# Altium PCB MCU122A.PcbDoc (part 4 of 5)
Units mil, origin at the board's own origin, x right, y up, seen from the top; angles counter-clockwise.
Board outline 4950 x 3450 mil, 4 copper layers (Top Layer, Signal Layer 1, Signal Layer 2, Bottom Layer), stack 60 mil thick; 257 components, 158 nets, 848 pads, 1971 vias.
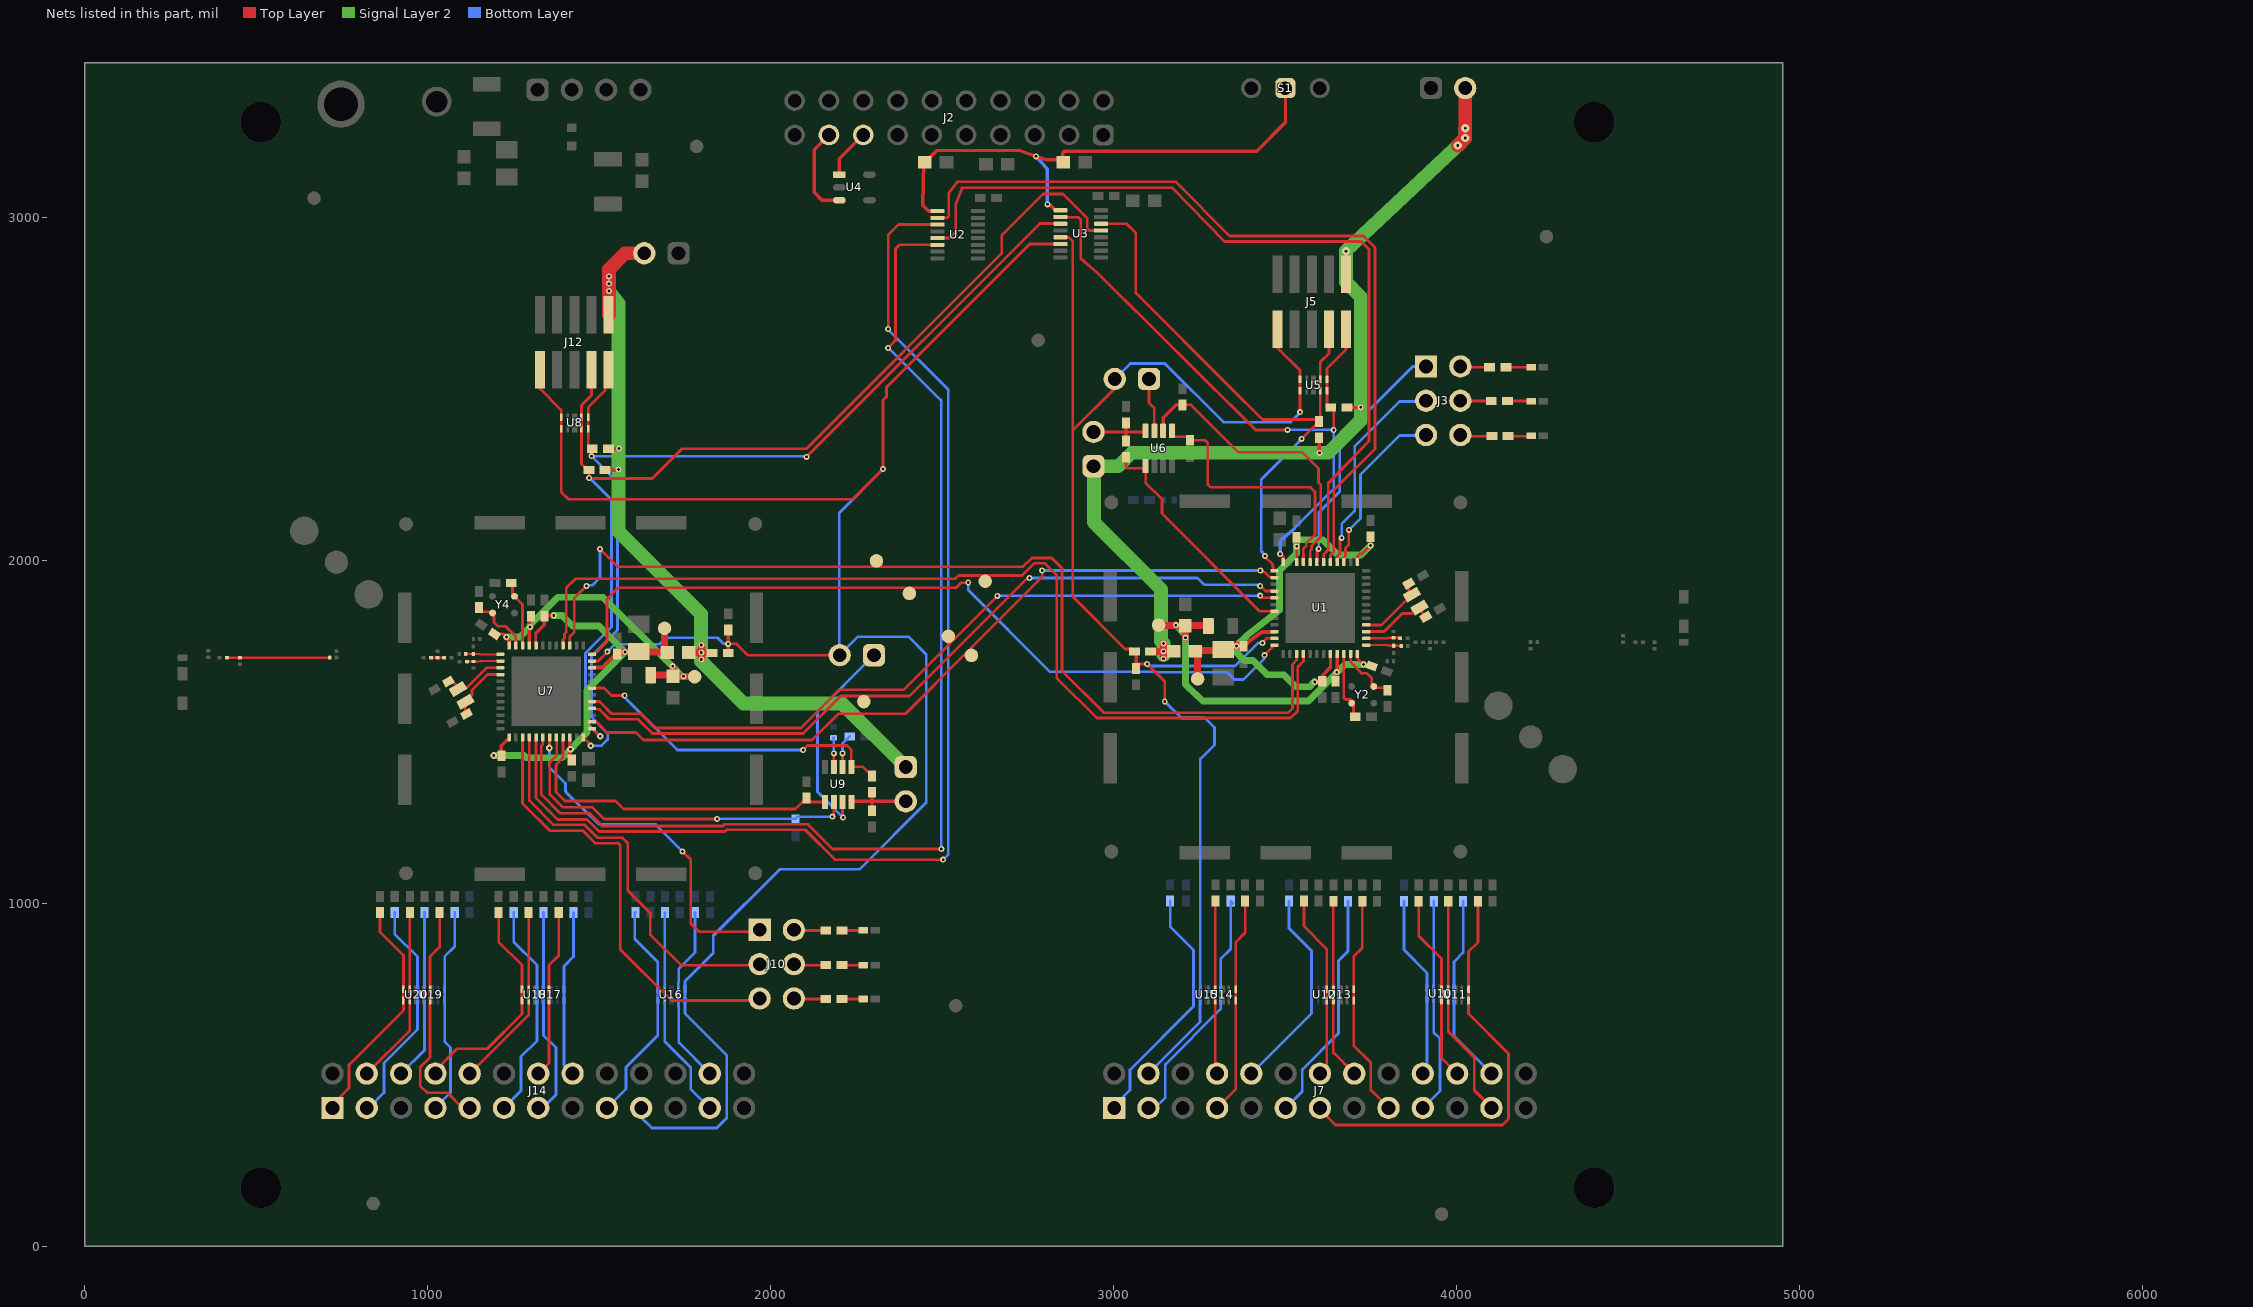
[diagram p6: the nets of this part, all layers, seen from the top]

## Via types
v1: diameter 17.46, hole 8, Top Layer to Bottom Layer, tented both sides, 1708 vias
v2: diameter 13.9, hole 8, Top Layer to Bottom Layer, tented both sides, 206 vias
v3: diameter 19.68, hole 8, Top Layer to Bottom Layer, tented both sides, 42 vias
v4: diameter 24, hole 8, Top Layer to Bottom Layer, tented both sides, 8 vias
v5: diameter 19.46, hole 8, Top Layer to Bottom Layer, tented both sides, 6 vias
v6: diameter 34, hole 8, Top Layer to Bottom Layer, tented both sides, 1 vias

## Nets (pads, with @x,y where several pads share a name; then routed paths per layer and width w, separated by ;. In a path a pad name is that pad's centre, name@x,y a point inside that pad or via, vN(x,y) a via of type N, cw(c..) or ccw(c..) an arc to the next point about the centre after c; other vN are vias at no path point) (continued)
NetC83_2: C83.2 C85.2 L11.1 | length 294.6
  Top Layer w6.5: L11.1@415.68,1715.3 C83.2@710.32,1715.3
NetC84_2: C84.2 L9.2 L10.1 | length 38
  Top Layer w6.5: L10.1@1010.16,1715.4 L9.2@1048.17,1715.4
NetC89_1: C89.1 U9.3 | length 85.3
  Top Layer w8: U9.3@2184.05,1397 v1(2184.05,1436.66)
  Bottom Layer w8: C89.1@2183,1481.9 2184.05,1480.84 v1(2184.05,1436.66)
NetC91_1: C91.1 U9.2 | length 103.2
  Top Layer w8: U9.2@2209.65,1397 v1(2209.65,1436.66)
  Bottom Layer w8: v1@2213.73,1440.75 v1(2209.65,1436.66) 2209.65,1465.33 C91.1@2230.22,1485.9
NetJ3_1: J3.1 U1.19 | length 725
  Top Layer w8: U1.19@3592.52,1994.09 3592.66,1994.23 3592.66,2027.71 v1(3597.57,2032.63)
  Bottom Layer w8: v1(3597.57,2032.63) 3597.57,2137.77 3659.13,2199.33 3659.13,2351.73 3871.94,2564.54 J3.1@3910.73,2564.54
NetJ3_2: J3.2 R12.1 | length 86.3
  Top Layer w8: J3.2@4010.73,2564.54 4013.06,2562.21 R12.1@4096.1,2562.21
NetJ3_3: J3.3 U1.16 | length 621.4
  Top Layer w8: U1.16@3650.87,1994.8 3650.87,2009.67 3659.69,2018.49 3659.69,2057.43 3664.66,2062.4 v1(3664.66,2064.96)
  Bottom Layer w8: v1(3664.66,2064.96) 3664.66,2104.91 3702.56,2142.8 3702.56,2331.55 3833.23,2462.21 3908.41,2462.21 J3.3@3910.73,2464.54
NetJ3_4: J3.4 R11.1 | length 90.3
  Top Layer w8: J3.4@4010.73,2464.54 4011.65,2463.62 R11.1@4100.65,2463.62
NetJ3_5: J3.5 U1.15 | length 513.5
  Top Layer w8: U1.15@3671.26,1994.09 3671.26,2007.61 3675.57,2011.92 3675.57,2034.53 3685.27,2044.23 3685.27,2087.51 v1(3685.89,2088.13)
  Bottom Layer w8: v1(3685.89,2088.13) 3719.38,2121.62 3719.38,2249.19 3833.23,2363.03 J3.5@3910.73,2363.03
NetJ3_6: J3.6 R10.1 | length 93.3
  Top Layer w8: J3.6@4010.73,2364.54 4013.99,2361.29 R10.1@4102.72,2361.29
NetJ8_1: J8.1 U6.7 | length 157.6
  Top Layer w8: J8.1@3103.15,2528 3103.15,2457.84 3118.43,2442.56 U6.7@3118.43,2376.74
NetJ10_1: J10.1 U7.19 | length 1020.8
  Top Layer w8: v5@1355.42,1450.42 U7.19@1355.42,1483.02 ; v1(1742.85,1150.5) 1766.87,1126.47 1766.87,940.29 1790.64,916.52 J10.1@1967.72,916.52
  Top Layer w10: v5@1355,1450 v5@1355.42,1450.42
  Bottom Layer w8: v5@1355,1450 1355.57,1398.12 1355.61,1394.85 1401.46,1349 1401.46,1325.49 1403.84,1323.12 1499.55,1229.49 1663.86,1229.49 v1(1742.85,1150.5)
  other v5: 1354.83,1451.79
NetJ10_2: J10.2 R36.1 | length 93.5
  Top Layer w8: J10.2@2067.72,921.8 2069.51,920.01 R36.1@2160.43,920.01
NetJ10_3: J10.3 U7.16 | length 1172.4
  Top Layer w8: U7.16@1296.36,1483.02 1296.36,1298.5 1366.97,1227.88 1458.01,1227.88 1495.73,1190.16 1567.86,1190.16 1583.23,1174.79 1583.23,1037.03 1648.6,971.66 1648.6,908.29 1738,818.9 J10.3@1967.72,818.9
NetJ10_4: J10.4 R35.1 | length 93.9
  Top Layer w8: J10.4@2067.72,821.8 2070.62,818.9 R35.1@2160.43,818.9
NetJ10_5: J10.5 U7.15 | length 1299.8
  Top Layer w8: U7.15@1276.68,1483.02 1276.68,1290.63 1356.6,1210.71 1452.73,1210.71 1489.34,1174.1 1556.78,1174.1 1561.47,1169.42 1561.47,1019.44 1561.47,865.08 1710.72,715.83 J10.5@1967.72,715.83
NetJ10_6: J10.6 R34.1 | length 93.3
  Top Layer w8: J10.6@2067.72,721.8 2069.05,720.48 R34.1@2160.43,720.48
NetJ15_1: J15.1 U9.7 | length 618.8
  Top Layer w8: U9.7@2209.65,1294.64 2209.65,1251.1 v1(2211.41,1249.33)
  Bottom Layer w8: v1(2211.41,1249.33) 2136.21,1324.53 2136.21,1557.74 J15.1@2301.14,1722.67
SW_CTRL: C10.1 C11.1 S1.1 U2.1 U3.1 | length 1597.5
  Top Layer w10: C10.1@2446.62,3160 2443.69,3034.98 2461.25,3017.41 U2.1@2485.91,3017.41 ; C10.1@2449.57,3160 2483.65,3194.07 2595.19,3194.07 2724.1,3194.16 v1(2773.31,3177.18) 2803.35,3166.81 2803.44,3166.9 2843.73,3166.9 2851.12,3174.29 2851.12,3187.26 2855.43,3191.57 3416.71,3191.57 3500.9,3275.76 S1.1@3500.9,3375.98 S1.1@3500.9,3384.19 ; v1(2806.73,3036.98) 2808.15,3035.56 2814.31,3035.56 2830.01,3019.86 U3.1@2838.47,3019.86
  Bottom Layer w10: v1(2773.31,3177.18) 2803.68,3143.17 2806.23,3140.32 2806.23,3037.48 v1(2806.73,3036.98)
VDDR_WM1: C26.1 C27.1 C28.1 L1.2 TP5.1 U1.45 U1.48 | length 1093.6
  Top Layer w8: C27.1@3647,1646.62 C27.1@3650,1649.62 ; U1.48@3710.63,1726.38 3710.63,1713.41 v1(3728.41,1695.63) ; v1(3728.41,1695.63) 3747.67,1695.63 C28.1@3752.22,1691.08 3732.96,1691.08 v1(3728.41,1695.63)
  Top Layer w10: C27.1@3650,1649.62 v1(3650,1672.95) ; v1@3651.57,1672.95 U1.45@3651.57,1726.38
  Top Layer w20: TP5.1@3131.94,1809.35 v1@3181.1,1809.35 ; v1@3183.31,1807.98 C26.1@3208.54,1807.98 3208.54,1774.43 v1(3209.4,1773.57) ; C26.1@3215.6,1809.29 L1.2@3267.17,1809.13
  Signal Layer 2 w20: v1(3181.1,1810.19) v1@3209.4,1781.89 ; v1@3209.4,1776.57 3209.4,1636.65 3213.6,1632.45 3259.76,1588.77 3556.86,1588.77 3568.21,1588.77 3675.07,1695.63 v1(3728.41,1695.63)
VDDR_WM2: C66.1 C67.1 C68.1 L7.2 TP13.1 U7.45 U7.48 | length 983.5
  Top Layer w10: C68.1@1194.85,1784.45 1220.65,1784.45 v1(1229.7,1775.4) ; 1222.1,1783 v1(1229.7,1775.4) ; U7.48@1237.31,1750.74 1237.31,1767.79 v1(1229.7,1775.4) ; U7.45@1296.36,1750.74 1296.36,1831.74 C67.1@1301,1836.38 ; C66.1@1710.85,1664.38 C66.1@1714.31,1660.93 ; TP13.1@1777.11,1660.93 TP13.1@1778.29,1659.75
  Top Layer w20: L7.2@1653.39,1664.38 C66.1@1710.85,1664.38 ; v1@1714.71,1690.46 C66.1@1714.71,1660.93 v1(1745.85,1660.93) TP13.1@1777.11,1660.93
  Signal Layer 2 w20: v1(1229.7,1775.4) 1268.4,1775.4 v1(1298,1805) 1298,1810.31 1379.15,1891.47 1511.02,1891.47 1713.17,1689.32 1741.56,1660.93 v1(1745.85,1660.93)
  other v1: 1714.31,1690.46
VDDS_WM1: C21.1 C22.1 C23.1 C24.1 C25.1 FB2.2 TP4.1 U1.13 U1.22 U1.34 U1.44 | length 1546.7
  Top Layer w8: U1.22@3533.46,1994.09 C25.1@3533.46,2076.77 ; 3631.89,1688.13 U1.44@3631.89,1726.38 ; U1.13@3710.63,1994.09 3710.63,2010.67 3717.68,2017.72 3723.12,2017.72 3747.72,2042.32 3747.72,2066.6 C23.1@3749.03,2067.91
  Top Layer w10: v1(3586.35,1644.58) 3588.39,1646.62 C24.1@3608,1646.62 3608,1662.83 3631.89,1686.72 3631.89,1688.13
  Top Layer w12: C21.1@3329.11,1750.39 3319.9,1741.18 C21.1@3342.11,1741.18 ; C22.1@3377.97,1750.39 3382.94,1750.39 3397.97,1765.42 3433.21,1790.5 U1.34@3468.5,1790.5
  Top Layer w20: TP4.1@3241.64,1653.57 3244.83,1656.76 3244.83,1736.22 C21.1@3304.15,1736.22 ; C21.1@3329.11,1750.39 C22.1@3377.97,1750.39
  Signal Layer 2 w20: v1@3585.48,1645.45 3570.52,1630.49 3531.22,1630.49 3496.28,1665.44 3448.17,1665.44 3406.01,1707.6 3380.54,1707.6 3356.32,1731.83 3356.32,1749.09 3357.21,1749.09 3387.3,1779.17 3483.11,1853.56 3483.11,1969.11 3533.46,2019.47 3533.46,2051.18 3541.51,2059.23 3608.59,2059.23 3653.32,2014.5 3720.66,2014.5 3748.49,2042.32 v1(3749.03,2042.32)
  other v1: 3358.32,1749.09 3533.46,2040
VDDS_WM2: C61.1 C62.1 C63.1 C64.1 C65.1 FB3.2 TP12.1 U7.13 U7.22 U7.34 U7.44 | length 1422
  Top Layer w8: 1314.94,1785.72 1314.94,1751.85 U7.44@1316.05,1750.74
  Top Layer w10: v5@1193.5,1427.58 1195.29,1429.37 C63.1@1214.77,1429.37 1214.77,1458.86 1237.31,1481.39 U7.13@1237.31,1483.02 ; 1314.66,1786 1339.44,1810.79 1340,1810.79 C64.1@1340,1836.38 1341.97,1838.35 v1@1363.65,1838.35 ; U7.22@1414.47,1483.02 1414.47,1418.15 C65.1@1420,1412.62
  Top Layer w12: U7.34@1479.43,1686.5 1509.19,1686.5 1551.02,1727.68 C62.1@1555.78,1732.37
  Top Layer w20: C62.1@1555.78,1732.37 1615.24,1732.37 1688.77,1732.37 1690.57,1730.57 1690.57,1800.95 TP12.1@1690.46,1801.06
  Signal Layer 2 w20: v5(1192.41,1430.32) 1280.44,1430.32 1287.36,1423.4 1390.9,1423.4 1464.83,1497.33 1464.83,1621.59 v1(1575.24,1732) 1499.74,1807.5 1422.75,1807.5 1392.91,1837.34 1392.91,1838.35 1365.45,1838.35 v1@1364.55,1837.45
  other v1: 1367.65,1838.35
  other v5: 1416.5,1448
WM1_2HOST_REV: J7.17 R1.2 U13.5 U13.6 | length 654.9
  Top Layer w8: R1.2@3724.87,1005.16 3724.73,1005.02 3724.73,869.35 3699.76,844.38 3699.76,771.05 3699.76,738.17 3699.76,584.34 3749.81,534.3 3749.81,454.33 J7.17@3801.38,402.76
WM1_2HOST_RTC: J7.20 R2.2 U10.5 U10.6 | length 539.7
  Top Layer w8: J7.20@3896.98,502.76 J7.20@3901.38,502.76
  Bottom Layer w8: R2.2@3846.14,1004.98 3846.14,863.71 3913.63,796.21 U10.6@3913.63,752.5 U10.5@3913.63,719.63 3913.63,515.01 J7.20@3901.38,502.76
WM1_GPIO_4: J7.23 R5.2 U11.2 U11.9 | length 660.8
  Top Layer w8: R5.2@3975.42,1005.19 R5.2@3975.42,1004.98 3975.42,625.63 4051.23,549.83 4051.23,454.09 4101.38,403.94 J7.23@4101.38,402.76
  Bottom Layer w8: J7.23@4095.14,402.76 J7.23@4101.38,402.76
WM1_GPIO_5: J7.1 R6.2 U15.5 U15.6 | length 727.4
  Bottom Layer w8: J7.1@3001.38,402.76 3001.38,407.97 3047.73,454.33 3047.73,513.67 3233.03,698.98 U15.6@3233.03,748.71 3233.03,863.11 3164.74,931.39 R6.2@3164.74,1005.93
WM1_GPIO_6: J7.13 R7.2 U11.5 U11.6 | length 1280.2
  Top Layer w8: J7.13@3601.38,402.76 3601.38,397.65 3646.27,352.76 4133.51,352.76 4151.36,370.61 4151.36,560.63 4034.57,677.43 4034.57,858.12 4061.86,885.41 R7.2@4061.86,1004.98
  Bottom Layer w8: J7.13@3601.38,397.65 J7.13@3601.38,402.76
WM1_GPIO_7: J7.11 R8.2 U12.1 U12.10 | length 677.8
  Bottom Layer w8: J7.11@3501.38,402.76 3549.98,451.36 3549.98,515.01 3655.36,620.4 U12.1@3655.36,715.83 U12.10@3655.36,748.71 3655.36,831.8 3682.93,859.37 R8.2@3682.93,1005.35
WM1_GPIO_8: J7.16 R9.2 U13.2 U13.9 | length 529.9
  Top Layer w8: R9.2@3640.76,1005.35 3640.48,1005.07 3640.48,563.65 J7.16@3701.38,502.76
  Bottom Layer w8: J7.16@3701.38,502.76 J7.16@3702.78,504.16
WM1_GPIO_24: J7.8 R14.2 U14.2 U14.9 | length 505.3
  Top Layer w8: R14.2@3296.27,1005.95 3296.27,507.86 J7.8@3301.38,502.76
WM1_GPIO_25: J7.3 R15.2 U15.1 U15.10 | length 723.1
  Bottom Layer w8: J7.3@3101.38,402.76 3120.49,402.76 3150.49,432.76 3150.49,529.42 3311.77,690.7 U15.10@3311.77,748.71 3311.77,836.5 3341.36,866.09 R15.2@3341.36,1005.53 R15.2@3348.2,998.7
WM1_GPIO_28: J7.10 R16.2 U12.5 U12.6 | length 602.6
  Bottom Layer w8: J7.10@3401.38,502.76 3576.88,678.26 3576.88,715.83 3576.88,748.71 3576.88,860.95 3511.35,926.47 R16.2@3511.35,1005.53
WM1_GPIO_30: J7.14 R18.2 U13.1 U13.10 | length 545.4
  Top Layer w8: R18.2@3554.61,1005.53 3554.61,932.9 3621.02,866.48 3621.02,771.05 3621.02,738.17 3621.02,522.41 J7.14@3601.38,502.76
  Bottom Layer w8: J7.14@3601.38,502.76 J7.14@3608.39,502.76
WM1_HOST2WM: J7.24 R13.2 U10.1 U10.10 | length 558.7
  Bottom Layer w8: R13.2@4018.88,1004.98 4018.88,855.49 3991.95,828.57 3991.95,752.5 3991.95,719.63 3991.95,612.18 J7.24@4101.38,502.76
WM1_LED_G: D1.2 R12.2 | length 74.1
  Top Layer w8: R12.2@4143.34,2562.21 D1.2@4217.42,2562.21
WM1_LED_O: D2.2 R11.2 | length 69.9
  Top Layer w8: R11.2@4147.89,2463.62 4216.51,2463.62 D2.2@4217.42,2462.71
WM1_LED_R: D3.2 R10.2 | length 67.5
  Top Layer w8: R10.2@4149.96,2361.29 4216.12,2361.29 D3.2@4217.05,2362.21
WM1_RF1_N: C47.2 L6.1 U1.2 | length 99.1
  Top Layer w6.5: U1.2@3736.44,1771.87 3800.18,1771.87 cw(c3803.27,1768.78) 3803.27,1773.15 C47.2@3816.03,1773.15 L6.1@3835.17,1773.15
WM1_RF1_P: C42.1 L2.1 U1.1 | length 102.9
  Top Layer w6.5: U1.1@3736.22,1751.97 3799.96,1751.97 ccw(c3804.41,1756.42) 3804.41,1750.13 L2.1@3816.03,1750.13 C42.1@3838.65,1750.13
WM1_RST_L: C48.1 J5.10 J7.4 J8.2 R21.1 U1.35 U3.5 U5.5 U5.6 U15.4 U15.7 | length 4312.1
  Top Layer w8: U3.5@2845.67,2940.22 2869.63,2940.22 2880.95,2928.9 2880.95,1892.86 3033.12,1740.69 R21.1@3053.69,1740.69 ; 2881.95,2378.54 3003.15,2499.75 J8.2@3003.15,2528 ; C48.1@3064.83,1696.55 3064.93,1696.65 v1(3097.78,1696.65) 3148.86,1645.57 v1(3148.86,1587.94) ; v1@3433.17,1759.35 3445.47,1771.65 U1.35@3468.5,1771.65 ; J5.10@3477.56,2672.64 3477.56,2618.65 3542.94,2553.27 3542.94,2526.96 U5.5@3543.22,2526.68 ; U5.5@3542.94,2526.68 3542.94,2481.97 3543.22,2481.69 v1@3543.22,2432.6
  Top Layer w10: U3.5@2844.77,2941.12 U3.5@2845.67,2940.22 ; R21.1@3053.69,1740.69 R21.1@3060.51,1733.87 ; R21.1@3061.32,1733.87 3065.51,1733.87 3065.51,1697.22 C48.1@3064.93,1696.65
  Bottom Layer w8: J8.2@3003.15,2528 3048.44,2573.28 3148.86,2573.28 3320.21,2401.94 3515.78,2401.94 v1@3544.83,2430.99 ; v1(3097.78,1696.65) 3098.36,1696.07 3098.36,1691.18 3353.27,1691.18 3420.45,1758.35 v1(3434.17,1758.35) ; J7.4@3101.38,502.76 3251.8,653.18 3251.8,715.83 U15.7@3251.8,748.71 ; v1(3148.86,1587.94) 3197.55,1539.25 3266.19,1539.25 3293.64,1511.8 3293.64,1460.67 3252.65,1419.68 U15.7@3252.72,748.71
  other v1: 3543.74,2430.99
WM1_TCK: J5.4 R19.1 U1.25 U3.14 U5.2 U5.9 | length 1758.9
  Top Layer w8: U3.14@2979.75,2979.59 2981.29,2979.59 2982.2,2980.49 3037.69,2980.49 3064.65,2953.53 3064.65,2778.53 3339.92,2503.27 3433.6,2409.58 3593.17,2409.58 R19.1@3598.74,2404.01 ; v1(3441.42,2011.92) 3441.42,2009.37 3462.6,1988.19 3463.18,1986.26 U1.25@3468.5,1968.5 ; v1@3548.7,2353.76 R19.1@3593.96,2399.01 ; R19.1@3598.23,2401.82 3598.68,2403.74 3598.73,2403.93 R19.1@3598.74,2404.01 ; R19.1@3598.85,2403.91 R19.1@3598.74,2404.01 ; R19.1@3602.35,2419.47 R19.1@3598.74,2404.01 ; 3602.35,2576.82 3627.56,2602.03 J5.4@3627.56,2672.64 ; R19.1@3602.5,2419.47 3602.5,2576.82
  Top Layer w10: R19.1@3596.76,2401.82 3598.68,2403.74 R19.1@3598.85,2403.91
  Bottom Layer w8: v1(3441.42,2011.92) 3441.42,2014.47 3430.22,2025.68 3430.22,2235.27 v1(3548.24,2353.3) v1@3549.22,2354.28
WM1_TMS: J5.2 R20.1 U1.24 U3.2 U5.1 U5.10 | length 1894.4
  Top Layer w8: U3.2@2844.77,3000.18 2845.9,2999.05 2897.92,2999.05 2903.82,2993.14 2903.82,2879.62 2952.99,2836.61 3414.13,2379.47 3414.37,2379.23 3444.75,2379.23 v1@3507.05,2379.17 ; R20.1@3622.03,2440.56 U5.10@3622.03,2493.81 U5.1@3622.03,2526.68 3622.03,2558.28 3677.56,2613.81 J5.2@3677.56,2672.64 ; v1(3641.34,2379.47) R20.1@3641.34,2444.67
  Top Layer w10: v1(3485.56,2017.72) 3494.09,2009.18 U1.24@3494.09,1994.09 ; v1@3507.05,2379.17 v1@3509.88,2379.17
  Bottom Layer w8: v1(3507.05,2379.55) 3641.26,2379.55 3641.26,2206.73 3526.06,2091.54
  Bottom Layer w10: v1@3485.56,2018.58 3485.56,2055.19 3488.49,2058.12 3488.7,2058.32 3488.92,2058.52 3526.06,2091.54
WM1_UART_RX_HOST: J7.22 R3.2 U11.1 U11.10 | length 548.7
  Top Layer w8: R3.2@3889.25,1004.98 3889.25,904.58 3955.39,838.43 3955.39,548.74 J7.22@4001.38,502.76
WM1_UART_RXD: U1.18 U2.5 | length 2420.3
  Top Layer w8: U2.5@2485.91,2938.67 2521.42,2938.67 2539.5,2956.75 2539.5,3036.98 2558.07,3085.18 3171.35,3085.18 3322.73,2928.9 3721.74,2928.9 3741.72,2908.92 3744.06,2906.57 3744.06,2346.52 3625.46,2223.82 3625.46,2029.97 3612.2,2016.71 U1.18@3612.2,1994.09
WM1_UART_TX_DONE_HOST: J7.7 R17.2 U14.5 U14.6 | length 636.8
  Top Layer w8: J7.7@3301.38,402.76 3355.51,456.89 U14.5@3355.51,715.83 U14.6@3355.51,748.71 3355.51,885.41 3383.39,913.29 R17.2@3383.39,1005.53
WM1_UART_TX_HOST: J7.19 R4.2 U10.4 U10.7 | length 633.5
  Top Layer w8: J7.19@3901.38,402.76 J7.19@3904.64,402.76
  Bottom Layer w8: J7.19@3901.38,402.76 3951.06,452.44 3951.06,605.14 3933.25,622.95 U10.4@3933.31,719.63 U10.7@3933.31,752.5 3933.25,789.08 3933.44,789.26 R4.2@3933.44,1004.98
WM1_UART_TXD: U1.17 U2.2 | length 2412.4
  Top Layer w8: U2.2@2485.91,2997.73 2514.49,2997.73 2519.45,3002.69 2519.45,3069.25 2544.13,3103.06 3179.7,3103.06 3337.98,2944.77 3728.68,2944.77 3761.93,2911.52 3761.93,2324.08 3641.34,2203.48 3641.34,2023.4 3631.89,2013.95 U1.17@3631.89,1994.09
WM1_VDD: FB2.1 J5.1 J6.2 J9.1 R19.2 R20.2 R21.2 | length 2871.9
  Top Layer w8: FB2.1@3171.62,1733.87 FB2.1@3173.96,1736.22
  Top Layer w10: v1@3598.85,2313.86 R19.2@3598.85,2356.66 ; J5.1@3677.56,2832.87 v4@3677.56,2892.41 ; R20.2@3688.05,2444.67 v1@3720.07,2444.67
  Top Layer w20: R21.2@3112.75,1733.87 v1@3139,1733.87 ; v1@3139.34,1733.87 v1(3145,1733.87) ; v1(3145,1712.22) v1(3145,1733.87) ; v1(3145,1756.37) v1(3145,1733.87) ; FB2.1@3171.62,1733.87 v1(3145,1733.87)
  Top Layer w40: v4(4003.37,3208.76) v4(4024.8,3230.19) v4(4024.8,3259.03) J6.2@4024.8,3375.98
  Signal Layer 2 w40: J9.1@2942.56,2260.32 2942.56,2109.92 3137.78,1914.7 3137.78,1763.59 v1(3145,1756.37) 3145.31,1756.07 3145.31,1722.08 ; J9.1@2953.62,2273.59 3013.67,2273.59 3052.74,2312.67 v1(3600.04,2312.67) 3626.3,2312.67 3720.07,2406.44 v1(3720.07,2445.24) 3720.07,2767.57 3677.5,2810.14 v4@3677.5,2899.61 ; v4@3676.89,2900.78 3993.37,3198.76 ; v4@3998.37,3203.76 v4(4003.37,3208.76) v4(4024.8,3230.19) v4(4024.8,3259.03)
  other v4: 3677.5,2900
WM1_WD_SET0: R22.1 U1.31 U6.1 | length 693.6
  Top Layer w8: R22.1@3036.11,2299.97 3036.11,2272.2 3040.51,2267.79 U6.1@3086.25,2267.79 ; U6.1@3092.84,2274.38 3093.11,2236.97 3093.11,2225.08 3140.78,2177.41 3140.78,2135.37 3425.46,1850.68 3468.21,1850.68 U1.31@3468.5,1850.39
  Top Layer w10: U6.1@3086.25,2267.79 U6.1@3092.84,2274.38
WM1_WD_SET1: R24.2 U1.21 U6.5 | length 793.7
  Top Layer w8: U6.5@3169.61,2376.74 3169.61,2364.93 3174.47,2360.07 3183.47,2360.07 3183.77,2359.78 R24.2@3222.5,2359.78 ; R24.2@3222.5,2349.18 3266.53,2349.18 3274.4,2341.31 3274.4,2220.49 3282.79,2212.1 3573.55,2212.1 3586.87,2198.78 3586.87,2073.52 3561.1,2047.74 3561.1,2040.97 3552.76,2032.63 3552.76,2027.56 3553.15,2008.2
  Top Layer w10: R24.2@3222.5,2349.18 R24.2@3222.5,2359.78 ; U1.21@3553.15,1994.09 3553.15,2008.2
WM1_WD_VDD: C50.1 J9.2 R22.2 U6.8 | length 201.3
  Top Layer w8: J9.2@2941.14,2373.59 3036.11,2373.59 ; R22.2@3036.11,2347.21 3036.11,2373.59 ; C50.1@3036.11,2399.97 3036.11,2373.59 ; U6.8@3089.69,2373.59 3036.11,2373.59
WM1_WDI: R23.2 U1.20 U6.6 | length 871.6
  Top Layer w8: R23.2@3200.1,2452.44 3224.89,2452.44 3362.91,2314.42 3549.22,2314.42 3597.31,2266.33 3597.31,2225.54 3603.83,2219.02 3603.83,2068.02 3576.97,2041.16 3576.97,2031.56 3572.83,2027.43 U1.20@3572.83,1994.09
  Top Layer w10: U6.6@3144.02,2376.74 3144.02,2414.4 3182.05,2452.44 R23.2@3200.1,2452.44
WM1_X32K_Q1: C36.1 U1.3 Y1.2 | length 216.8
  Top Layer w8: U1.3@3736.22,1791.34 3788.73,1791.34 3841.4,1844 3869.4,1844 3886.97,1861.58 Y1.2@3891.33,1861.58 3891.33,1854.73 C36.1@3909.54,1836.52
WM1_X32K_Q2: C35.1 U1.4 Y1.1 | length 199
  Top Layer w8: U1.4@3736.22,1811.02 3736.89,1810.35 3780.95,1810.35 Y1.1@3869.68,1899.08 ; Y1.1@3860.54,1900.71 C35.1@3860.54,1929.19
WM1_X48M_N: C38.1 U1.46 Y2.3 | length 207.1
  Top Layer w8: U1.46@3671.26,1726.38 3670.82,1725.94 3670.82,1598.44 3675.51,1593.75 3692,1593.75 3699.43,1586.33 3699.43,1547.95 C38.1@3704.38,1543
WM1_X48M_P: C37.1 U1.47 Y2.1 | length 181.3
  Top Layer w8: U1.47@3690.94,1726.38 3690.94,1702.16 3722.79,1670.32 3737.67,1670.32 3752.57,1655.41 3752.57,1627.67 3790.95,1627.67 C37.1@3798,1620.62
WM2_2HOST_REV: J14.16 R25.2 U17.1 U17.10 | length 493.3
  Top Layer w8: J14.16@1422.44,502.76 J14.16@1424.34,502.76
  Bottom Layer w8: J14.16@1422.44,502.76 1397.18,528.02 U17.1@1397.18,715.83 U17.10@1397.18,748.71 1397.18,815.75 1424.97,843.55 R25.2@1424.97,972.2
WM2_2HOST_RTC: J14.13 R26.2 U17.4 U17.7 | length 613.4
  Bottom Layer w8: J14.13@1322.44,402.76 1335.53,402.76 1373.95,441.18 1373.95,578.33 1337.97,614.31 1337.97,715.83 1337.97,748.71 R26.2@1337.97,972.2
WM2_GPIO_4: J14.4 R29.2 U20.2 U20.9 | length 527.6
  Top Layer w8: J14.4@822.44,502.76 947.97,628.28 R29.2@947.97,972.2
  Bottom Layer w10: J14.4@822.44,502.76 J14.4@826.77,507.09
WM2_GPIO_5: J14.9 R30.2 U20.5 U20.6 | length 699.9
  Top Layer w8: R30.2@1034.97,972.2 1034.97,871.59 1006.95,843.57 1006.95,549.99 978.09,521.13 978.09,466.62 997.59,447.11 1040.81,447.11 1040.92,447 1057.32,447 1101.56,402.76 J14.9@1122.44,402.76
WM2_GPIO_6: J14.8 R31.2 U18.1 U18.10 | length 653.8
  Top Layer w8: J14.8@1022.44,502.76 1022.44,512.25 1085.3,575.11 1173.63,575.11 1274.79,676.26 U18.1@1274.79,715.83 U18.10@1274.79,748.71 1274.79,818.9 1206.97,886.72 R31.2@1206.97,972.2
WM2_GPIO_7: J14.10 R32.2 U18.2 U18.9 | length 559.7
  Top Layer w8: J14.10@1122.44,502.76 1123.73,502.76 1294.35,673.37 R32.2@1294.35,971.82 ; R32.2@1293.97,972.2 R32.2@1294.35,971.82 ; R32.2@1296.25,969.92 R32.2@1294.35,971.82
  Bottom Layer w8: J14.10@1122.44,502.76 J14.10@1133.34,513.65
WM2_GPIO_8: J14.14 R33.2 U18.5 U18.6 | length 494.1
  Top Layer w8: J14.14@1322.44,502.76 1353.84,534.16 1353.84,818.9 1381.97,847.03 R33.2@1381.97,972.2
WM2_GPIO_24: J14.3 R38.2 U19.5 U19.6 | length 661.9
  Bottom Layer w8: J14.3@822.44,402.76 828.43,402.76 872.78,447.11 872.78,533.62 970.33,631.17 970.33,715.83 970.33,748.71 970.33,843.57 903.71,910.18 R38.2@903.71,971.94
  Bottom Layer w10: R38.2@903.71,971.94 R38.2@903.97,972.2
WM2_GPIO_25: J14.23 R39.2 U16.4 U16.7 | length 595.8
  Bottom Layer w8: U16.4@1690.97,708.71 1690.97,596.95 1766.8,521.13 1766.8,458.4 J14.23@1822.44,402.76 ; U16.4@1690.97,722.95 U16.7@1690.97,741.58 ; U16.7@1690.97,755.83 1690.97,859.91 1690.97,971.2 R39.2@1691.97,972.2
WM2_GPIO_28: J14.17 R40.2 U16.5 U16.6 | length 659.7
  Bottom Layer w8: J14.17@1522.44,402.76 1578.09,458.4 1578.09,521.13 1670.8,613.84 1670.8,828.55 1603.41,895.94 1603.41,970.15 R40.2@1605.46,972.2
WM2_GPIO_30: J14.7 R42.2 U19.1 U19.10 | length 617.1
  Top Layer w10: J14.7@1022.44,402.76 J14.7@1022.44,412.65
  Bottom Layer w8: J14.7@1022.44,402.76 1066.8,447.11 1066.8,578.63 1049.53,595.9 U19.1@1049.53,715.83 U19.10@1049.53,748.71 1049.53,843.57 1078.97,873.01 R42.2@1078.97,972.2
WM2_HOST2WM: J14.24 R37.2 U16.2 U16.9 | length 499.2
  Bottom Layer w8: U16.2@1730.47,708.71 1730.47,701.1 1732.18,699.39 1732.18,593.02 J14.24@1822.44,502.76 ; U16.2@1730.47,722.95 U16.9@1730.47,741.58 ; U16.9@1730.47,755.83 1730.47,768.04 1732.18,769.75 1732.18,808.77 1779.02,855.61 R37.2@1779.02,972.2
WM2_LED_G: D4.2 R36.2 | length 62
  Top Layer w8: R36.2@2207.68,920.01 2268.99,920.01 D4.2@2269.47,920.49
WM2_LED_O: D5.2 R35.2 | length 61.8
  Top Layer w8: R35.2@2207.68,818.9 D5.2@2269.47,818.9
WM2_LED_R: D6.2 R34.2 | length 61.8
  Top Layer w8: R34.2@2207.68,720.48 D6.2@2269.47,720.48
WM2_RF1_N: C87.2 L12.1 U7.2 | length 96
  Top Layer w6.5: L12.1@1114.96,1704.12 C87.2@1133.36,1704.12 1144.69,1704.12 ; 1144.71,1704.14 1152.43,1704.14 ccw(c1152.43,1708.16) 1155.27,1705.32 U7.2@1210.65,1705.32
WM2_RF1_P: C82.1 L8.1 U7.1 | length 95.2
  Top Layer w6.5: 1115.9,1726.45 L8.1@1133.36,1726.45 1144.71,1726.45 1150.05,1726.45 cw(c1150.05,1720.93) 1153.95,1724.83 U7.1@1210.66,1724.99
WM2_RST_L: C88.1 J12.10 J14.19 J15.2 R45.1 U3.6 U7.35 U8.5 U8.6 U16.1 U16.10 | length 6130.2
  Top Layer w8: J12.10@1327.37,2554.79 1327.37,2499.54 1389.03,2437.89 U8.5@1389.03,2416.13 1389.03,2198.27 1409.89,2177.41 2240.02,2177.41 v1(2327.77,2265.16) 2327.77,2466.16 2337.66,2476.06 2337.66,2503.76 2755.35,2921.44 U3.6@2844.77,2921.44 ; U7.35@1479.43,1705.46 1497.14,1705.46 v1@1523.68,1732 ; v1(1876.19,1755.82) 1900.22,1755.82 1933.96,1722.08 2199.46,1722.08 J15.2@2199.82,1721.72
  Top Layer w10: R45.1@1876.15,1728.73 1876.15,1750.79 v1@1877.19,1751.82 ; v1@1876.19,1752.82 v1(1876.19,1755.82) 1876.19,1778.41
  Bottom Layer w8: v1(1523.68,1733) 1545.53,1754.85 1675.25,1754.85 1693.83,1773.43 1845.28,1773.43 1862.88,1755.83 v1(1876.19,1755.82) ; J14.19@1622.44,402.76 1622.44,375.43 1653.39,344.49 1842.65,344.49 1872.24,374.08 1872.24,555.87 1750.09,678.03 U16.1@1750.09,715.83 U16.10@1750.09,748.71 1750.09,771.96 1832.63,854.51 1832.63,904.63 2026.29,1098.28 2259,1098.28 2453.6,1292.89 2453.6,1724.83 2401.86,1776.57 2255.05,1776.57 J15.2@2201.14,1722.67 ; J15.2@2199.82,1722.67 2199.82,2137.21 v1(2327.77,2265.16)
WM2_TCK: J12.4 R43.1 U3.13 U7.25 U8.2 U8.9 | length 3132.1
  Top Layer w8: v1@1470.98,2239.21 1470.98,2261.36 1467.28,2261.36 1448.08,2280.56 1448.08,2368.31 1448.14,2368.31 1448.14,2431.02 1448.08,2431.08 1448.08,2451.24 1477.37,2480.53 J12.4@1477.37,2554.79 ; v1@1474.42,2237.61 1654.68,2237.61 1741.58,2324.51 2104.59,2324.51 2673.48,2893.4 2673.48,2945.94 2794.42,3066.89 2852.53,3066.89 2923.21,2996.2 2923.21,2965.82 2927.9,2961.13 2962.56,2961.13 U3.13@2962.88,2960.81 ; U7.25@1479.43,1508.61 v5@1502.14,1485.9
  Top Layer w10: v1@1470.98,2239.21 1472.82,2239.21 v1@1474.42,2237.61 ; v5@1502.14,1485.9 v5(1503.17,1485.9)
  Bottom Layer w8: v1@1470.98,2240.64 1535.73,2175.89 1535.73,1804.55 1459.83,1728.65 1459.83,1529.25 v5(1503.17,1485.9)
  other v1: 1470.8,2239.21
WM2_TMS: J12.2 R44.1 U3.3 U7.24 U8.1 U8.10 | length 2929.6
  Top Layer w8: U7.24@1453.84,1482.29 v5@1477.47,1458.66 ; R44.1@1467.77,2322.38 U8.10@1467.77,2383.26 1467.77,2444.48 1517.49,2494.21 1517.49,2544.9 J12.2@1527.37,2554.79 ; v1(2104.33,2301.06) 2104.33,2301.17 2784.57,2981.41 2843.85,2981.41 U3.3@2844.77,2980.49
  Top Layer w10: U7.24@1453.84,1482.29 U7.24@1453.84,1483.02 ; v1@1478.72,2304.28 v1(1477.29,2302.85) 1477.29,2322.27 R44.1@1479.53,2324.51
  Bottom Layer w8: v1(1477.29,2302.85) 1553.6,2226.54 1553.6,1796.45 1477.7,1720.55 1477.7,1541.93 1524.77,1494.85 1524.77,1476.96 1506.72,1458.9 v5@1477.7,1458.9 ; v1@1478.64,2302.85 2102.54,2302.85 v1(2104.33,2301.06)
  Bottom Layer w10: v1(1477.29,2302.85) v1@1478.64,2302.85 ; v5@1477.47,1458.66 v5@1477.7,1458.9
  other v5: 1475.47,1458.66
WM2_UART_RX_HOST: J14.11 R27.2 U17.5 U17.6 | length 637.2
  Bottom Layer w8: J14.11@1222.44,402.76 1272.32,452.63 1272.32,552.06 1318.44,598.19 1318.44,678.68 1318.35,678.77 1318.35,715.83 1318.35,748.71 1318.35,818.9 1250.97,886.28 R27.2@1250.97,972.2
WM2_UART_RXD: U2.6 U7.18 | length 3356.3
  Top Layer w8: U7.18@1334.81,1482.1 U7.18@1335.73,1483.02 1335.73,1462.7 1331.4,1458.36 1331.4,1315.87 1385.51,1261.76 1471.86,1261.76 1508.86,1224.76 1860.11,1224.76 1864.84,1229.49 2107.22,1229.49 2108.07,1228.63 2109.25,1228.63 2180.16,1157.72 2497.23,1157.72 v1(2497.32,1157.62) ; v1(2342.52,2618.11) 2364.12,2639.72 2364.12,2907.54 2375.74,2919.16 U2.6@2485.91,2919.16
  Top Layer w10: U2.6@2485.91,2918.99 U2.6@2485.91,2919.16
  Bottom Layer w8: v1@2344.06,2618.11 2494.02,2468.15 2497.32,2464.85 v1(2497.32,1157.62)
  Bottom Layer w10: v1(2342.52,2618.11) v1@2344.06,2618.11
WM2_UART_TX_DONE_HOST: J14.6 R41.2 U19.4 U19.7 | length 499
  Bottom Layer w8: J14.6@922.44,502.76 990.41,570.73 R41.2@990.41,973.61
WM2_UART_TX_HOST: J14.1 R28.2 U20.1 U20.10 | length 703
  Top Layer w8: J14.1@722.44,402.76 722.44,412.89 770.63,461.08 770.63,528.39 929.14,686.9 929.14,847.42 860.97,915.6 R28.2@860.97,972.2
  Bottom Layer w10: J14.1@722.44,402.76 J14.1@722.44,422.44
WM2_UART_TXD: U2.3 U7.17 | length 3498.6
  Top Layer w8: U7.17@1316.05,1483.02 1315.52,1482.5 1315.52,1306.47 1378.1,1243.89 1464.45,1243.89 1499.46,1208.89 1866.69,1208.89 1871.41,1213.61 2100.65,1213.61 2187.79,1126.47 v1(2502.77,1126.47) ; v1(2342.52,2673.35) 2342.52,2947.52 2373.04,2978.04 U2.3@2485.91,2978.04
  Bottom Layer w8: v1@2342.52,2671.96 2518.02,2496.46 2518.02,1141.72 v1(2502.77,1126.47)
  Bottom Layer w10: v1@2342.52,2671.96 v1(2342.52,2673.35)
WM2_VDD: FB3.1 J12.1 J13.2 J16.1 R43.2 R44.2 R45.2 | length 2407.2
  Top Layer w10: R43.2@1517.31,2262.29 1554.92,2262.29 v1(1556.37,2263.73) ; R44.2@1526.77,2324.51 1557.15,2324.51 v1(1558.03,2325.38)
  Top Layer w11: R45.2@1827.07,1730.57 R45.2@1828.91,1728.73
  Top Layer w20: FB3.1@1761.43,1730.57 R45.2@1827.07,1730.57 ; v1(1797.85,1710) v1(1797.85,1752)
  Top Layer w40: J12.1@1528.33,2715.98 v1@1528.33,2784.33 ; v1@1528.33,2785.32 v1(1528.33,2805.83) v1@1528.33,2827.32 ; v1(1528.5,2827.32) 1528.5,2847.47 1575.5,2894.48 J13.2@1631.5,2894.48 J13.2@1626.72,2899.25
  Signal Layer 2 w40: v1@1528.52,2784.01 1555.18,2749.98 ; v1(1528.5,2827.32) 1528.68,2827.14 v1(1528.68,2784.33) ; v1@1556.26,2327.14 1556.26,2748.22 ; v1@1556.37,2323.72 v1(1556.37,2263.73) 1556.37,2083.39 1797.03,1842.73 v1@1797.03,1710 ; v1@1797.03,1705.33 1920.43,1581.93 2208.16,1581.93 J16.1@2393.7,1396.39 ; v1(1797.85,1710) v1(1797.85,1730.57)
WM2_WD_SET0: R46.1 U7.31 U9.1 | length 964.9
  Top Layer w8: U7.31@1479.43,1626.72 1513.88,1626.72 1535.55,1605.05 v1(1574.19,1605.05) ; v1(2094.73,1446.23) 2107.9,1459.39 2222.16,1459.39 2235.24,1446.32 U9.1@2235.24,1397 2268.53,1397 R46.1@2295.28,1370.25
  Bottom Layer w8: v1(1574.19,1605.05) 1574.19,1599.92 1727.89,1446.23 v1(2094.73,1446.23)
WM2_WD_SET1: R48.2 U7.21 U9.5 | length 991.2
  Top Layer w8: U7.21@1394.79,1483.02 1394.79,1423.87 1373.95,1403.04 1373.95,1323.87 1400.31,1297.51 1547.87,1297.51 1571.26,1274.13 2072.01,1274.13 R48.2@2104.33,1306.45
  Top Layer w10: R48.2@2104.33,1306.45 2116.14,1294.64 U9.5@2158.46,1294.64
WM2_WD_VDD: C90.1 J16.2 R46.2 U9.8 | length 218.7
  Top Layer w10: U9.8@2231.38,1298.5 U9.8@2235.24,1294.64 2236.99,1296.39 2295.28,1296.39 ; C90.1@2295.28,1268.98 2295.28,1296.39 ; R46.2@2295.28,1323.01 2295.28,1296.39 ; J16.2@2393.7,1296.39 2295.28,1296.39
WM2_WDI: R47.2 U7.20 U9.6 | length 1074.8
  Top Layer w8: U7.20@1376.6,1481.52 1376.6,1430.96 1356.08,1410.44 1356.08,1316.47 1392.91,1279.64 1479.26,1279.64 1513.53,1245.36 v1(1844,1245.36) ; v1(2179.81,1251.79) 2179.81,1254.35 2184.05,1258.6 U9.6@2184.05,1294.64
  Bottom Layer w8: v1(1844,1245.36) 1844.05,1245.41 2072.01,1245.41 2072.01,1246.69 2077.12,1251.79 v1(2179.81,1251.79)
WM2_X32K_Q1: C76.1 U7.3 Y3.2 | length 182.3
  Top Layer w8: C76.1@1068.46,1648.81 1087.99,1629.28 Y3.2@1087.99,1623.97 1090.65,1626.62 1092.58,1628.56 1114.24,1628.56 1171.46,1685.78 U7.3@1211.72,1685.78
WM2_X32K_Q2: C75.1 U7.4 Y3.1 | length 177.9
  Top Layer w8: C75.1@1117.06,1555.51 1109.65,1562.92 Y3.1@1109.65,1586.46 1129.43,1606.24 1129.43,1621.29 1174.23,1666.09 U7.4@1211.72,1666.09
WM2_X48M_N: C78.1 U7.46 Y4.3 | length 201.4
  Top Layer w8: C78.1@1243.62,1933.5 1247.57,1929.55 1247.57,1890.67 1256.01,1890.67 1276.68,1870 U7.46@1276.68,1750.74
WM2_X48M_P: C77.1 U7.47 Y4.1 | length 188.3
  Top Layer w8: C77.1@1149.5,1861.38 1161.55,1849.33 Y4.1@1193.43,1849.33 ; Y4.1@1194.43,1849.33 Y4.1@1193.43,1849.33 ; U7.47@1256.99,1750.74 1256.99,1777.25 1227.56,1806.68 1204.57,1806.68 1193.43,1817.83 Y4.1@1193.43,1849.33
WM2WM_SF_INT: TP9.1 U1.36 U7.36 | length 2329.7
  Top Layer w8: U7.36@1479.43,1725.15 1485.8,1725.15 1522.47,1761.82 1522.47,1886.91 1554.86,1919.29 2402.95,1919.29 2540.7,1919.29 2555.24,1933.84 2575.16,1933.84 v1(2575.97,1934.65) ; v1@3442.62,1718.23 3442.62,1726.08 U1.36@3468.5,1751.97
  Bottom Layer w8: v1(2575.97,1934.65) 2575.97,1912.22 2814.22,1673.97 3122.88,1673.97 3123.11,1673.74 3279.9,1672.95 3331.36,1672.95 3352.82,1651.49 3377.95,1651.49 3437.96,1711.5 3437.96,1720.69 v1(3439.77,1722.5)
WM2WM_SPI_CS: TP8.1 U1.29 U7.29 | length 2183.5
  Top Layer w8: U7.29@1479.43,1587.35 1500.41,1587.35 1535.96,1551.81 1619.93,1551.81 1661.61,1510.13 2088.16,1510.13 2199.69,1621.66 2386.9,1621.66 v1(2660.78,1895.54) ; v1(3426.96,1895.97) 3433.17,1889.76 U1.29@3468.5,1889.76
  Bottom Layer w8: v1(2660.78,1895.54) 2661.21,1895.97 v1(3426.96,1895.97)
WM2WM_SPI_MISO: TP10.1 U1.39 U7.39 | length 2909.2
  Top Layer w8: U7.39@1414.47,1750.74 1414.47,1777.33 1427.57,1790.43 1427.57,1889.43 1444.25,1906.11 v1(1462.66,1924.51) ; v1(1502.14,2032.24) 1553.6,1980.78 2736.06,1980.78 2761.49,2006.22 2819.41,2006.22 2849.54,1976.09 2849.54,1676.6 2971.01,1555.12 3509.21,1555.12 3521.02,1566.93 3521.02,1695.56 3533.46,1708.01 U1.39@3533.46,1726.38
  Bottom Layer w8: v1(1462.66,1924.51) 1464.47,1926.32 1479.7,1926.32 1502.14,1948.76 v1(1502.14,2032.24)
WM2WM_SPI_MOSI: TP7.1 U1.28 U7.28 | length 2223.1
  Top Layer w8: U7.28@1479.77,1567.67 1486.32,1567.67 1489.21,1564.78 1500.54,1564.78 1529.38,1535.93 1613.35,1535.93 1655.04,1494.25 2094.73,1494.25 2204.2,1603.72 2404.96,1603.72 2749.24,1948 v1(2754.86,1948) ; v1(3426.96,1924.46) 3427.61,1924.46 3442.62,1909.45 U1.28@3468.5,1909.45
  Bottom Layer w8: v1(2754.86,1948) 3243.81,1948 3263.66,1928.15 3417.55,1928.15 3419.43,1926.26 3425.15,1926.26 v1(3426.96,1924.46)
WM2WM_SPI_SCK: TP6.1 U1.26 U7.26 | length 2234.6
  Top Layer w8: U7.26@1479.43,1528.3 1480.36,1527.38 1493.04,1527.38 1522.86,1497.56 1606.83,1497.56 1629.12,1475.27 2120.64,1475.27 2197.18,1551.81 2392.49,1551.81 2573.9,1733.21 2579.86,1739.18 2791.36,1950.68 v1(2791.36,1969.74) ; v1(3427.61,1969.49) 3439.85,1964.57 3455.6,1948.82 U1.26@3468.5,1948.82
  Bottom Layer w8: v1(2791.36,1969.74) 2791.62,1969.49 v1(3427.61,1969.49)
WM2WM_SRDY: TP11.1 U1.40 U7.40 | length 2878.9
  Top Layer w8: U7.40@1394.79,1750.74 1394.79,1767.98 1398.6,1771.79 1398.6,1784.41 1403.66,1789.47 1403.66,1918.71 1430.34,1945.4 2537.67,1945.4 2547.52,1955.25 2732.98,1955.25 2768.07,1990.34 2799.9,1990.34 2833.66,1956.58 2833.66,1656.47 2950.88,1539.25 3515.78,1539.25 3536.56,1560.03 3536.89,1560.03 3536.89,1688.99 3553.15,1705.24 U1.40@3553.15,1726.38
XDS_BOARDID_SCL: J2.15 U4.1 | length 144.4
  Top Layer w10: U4.1@2200.18,3123.84 2200.18,3169.66 J2.15@2269.88,3239.36
XDS_BOARDID_SDA: J2.17 U4.3 | length 268.4
  Top Layer w10: J2.17@2169.88,3239.36 2126.56,3196.04 2126.56,3072.04 2149.56,3049.04 U4.3@2200.18,3049.04
pads on no net: FID1.1 FID2.1 FID3.1 FID4.1 FID5.1 FID6.1 FID7.1 FID8.1 FID9.1 FID10.1 FID11.1 FID12.1 J1.4 J2.2 J2.3 J2.4 J2.5 J2.9 J2.11 J5.6 J5.7 J5.8 J5.9 J7.6 J7.9 J12.6 J12.7 J12.8 J12.9 J14.20 J14.22 MP5. MP6. MP7. MP8. SH-J1.0 SH-J2.0 SH-J3.0 SH-J4.0 SH-J5.0 SH-J6.0 SH-J7.0 SH-J8.0 SH-J9.0 SH-J10.0 SH-J11.0 SH-J12.0 SH-J13.0 U1.27 U1.30 U5.3@3582.66,2526.68 U5.4 U5.7 U5.8@3582.66,2493.81 U7.27 U7.30 U8.3@1428.4,2416.13 U8.4 U8.7 U8.8@1428.4,2383.26 U10.2 U10.3@3953,719.63 U10.8@3953,752.5 U10.9 U11.3@3995.17,715.83 U11.4 U11.7 U11.8@3995.17,748.71 U12.2 U12.3@3615.99,715.83 U12.4 U12.7 U12.8@3615.99,748.71 U12.9 U13.3@3660.4,715.83 U13.4 U13.7 U13.8@3660.4,748.71 U14.1 U14.3@3316.14,715.83 U14.4 U14.7 U14.8@3316.14,748.71 U14.10 U15.2 U15.3@3272.4,715.83 U15.8@3272.4,748.71 U15.9 U16.3@1710.72,715.83 U16.8@1710.72,748.71 U17.2 U17.3@1357.81,715.83 U17.8@1357.81,748.71 U17.9 U18.3@1314.16,715.83 U18.4 U18.7 U18.8@1314.16,748.71 U19.2 U19.3@1010.16,715.83 U19.8@1010.16,748.71 U19.9 U20.3@967.76,715.83 U20.4 U20.7 U20.8@967.76,748.71
copper on no net: | length 1156.1
  Top Layer w0: 721.58,1948.76 cw(c734,1995.13) 746.42,1948.76 ; 4203.23,1530.47 ccw(c4215.25,1484) 4228.08,1530.25
  Signal Layer 1 w0: 782,1995.1 ccw(c734,1995.1) 782,1995.1 ; 4263.09,1484.19 ccw(c4215.09,1484.19) 4263.09,1484.19
  other v1: 2986.67,1753.18

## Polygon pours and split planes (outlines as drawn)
3V3_XDS on Signal Layer 2 "SIGNAL_LAYER_2_3V3_XDS_P010" (solid, pour order 10): 3214.29,2846.22 2181.69,2846.22 2181.69,3203.35 1917.45,3203.35 1917.45,3438.14 1922.04,3442.73 3214.29,3444.88
GND on Signal Layer 2 "SIGNAL_LAYER_2_GND_P022" (solid, remove dead copper, pour order 22): 294.1,3428.07 297.66,3424.51 4649.04,3424.51 4649.04,25.49 298.81,25.49 298.81,3424.37
GND on Bottom Layer "BOTTOM_LAYER_GND_P021" (solid, remove dead copper, pour order 21): 298.96,3424.51 4649.04,3424.51 4649.04,25.49 298.81,25.49 298.81,3424.37
GND on Top Layer "TOP_LAYER_GND" (solid, remove dead copper, pour order 12): 298.96,1732.5 298.96,3450.03 299.12,3449.87 4649.04,3449.87 4649.04,-0.17 4648.99,-0.22 4648.73,0.04 298.81,0.04 298.81,1732.38 298.61,1732.58
GND on Signal Layer 1 "SIGNAL_LAYER_1_GND_P011" (solid, remove dead copper, pour order 11): 294.1,3428.07 297.66,3424.51 4649.04,3424.51 4649.04,25.49 298.82,25.49 298.82,3424.37

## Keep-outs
Keep-Out Layer:
  text ".Layer_Name" at 577,-858.49 h60

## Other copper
Top Layer:
  rectangle net NetANT2_1: 265.75,1706.27 278.82,1724.38
  rectangle net NetANT2_1: 265.75,1649.19 278.21,1688.56
  rectangle net NetANT2_1: 265.75,1562.57 276.49,1601.94
  pour cut-out: 79.36,2298.53 80.89,2294.86 80.89,1654.38 141.36,1654.38 141.36,1688.56 142.88,1692.23 146.56,1693.75 174.72,1693.75 209.02,1728.06 212.7,1729.58 265.75,1729.58 272.56,1729.58 272.96,1729.74 298.11,1729.74 299.06,1729.35 300.1,1729.35 301.62,1728.72 303.03,1727.31 304.43,1725.9 304.69,1725.28 392.46,1725.29 393.42,1724.9 394.45,1724.9 397.51,1723.63 398.92,1722.22 400.32,1720.82 401.59,1717.76 401.59,1713.78 400.33,1710.72 398.92,1709.31 397.51,1707.91 394.45,1706.64 393.42,1706.64 392.46,1706.24 305.05,1706.23 304.43,1704.75 303.03,1703.35 301.62,1701.94 300.1,1701.31 299.06,1701.31 298.11,1700.91 272.96,1700.91 272.56,1701.08 270.97,1701.08 222.33,1701.08 199.39,1678.14 199.39,1562.57 197.87,1558.9 194.19,1557.38 146.56,1557.38 142.88,1558.9 141.36,1562.57 141.36,1596.75 120.26,1596.75 120.26,1378.79 214.98,1378.79 214.98,1688.56 216.5,1692.23 220.18,1693.75 270.97,1693.75 278.21,1693.75 281.89,1692.23 283.41,1688.56 283.41,1649.19 281.89,1645.51 278.21,1643.99 276.16,1643.99 276.16,1607.14 276.49,1607.14 280.16,1605.62 281.69,1601.94 281.69,1562.57 280.16,1558.9 276.49,1557.38 276.16,1557.38 276.16,1287.77 274.64,1284.09 270.97,1282.57 28.05,1282.57 24.38,1284.09 22.86,1287.77 22.86,2294.86 24.38,2298.53 28.05,2300.05 75.69,2300.05
  pour cut-out: 711.28,1724.43 712.31,1724.43 715.37,1723.16 716.78,1721.76 718.18,1720.35 719.45,1717.29 719.45,1713.31 718.18,1710.25 716.78,1708.84 715.37,1707.44 712.31,1706.17 711.28,1706.17 710.32,1705.77 415.68,1705.77 414.73,1706.17 413.69,1706.17 410.63,1707.44 409.23,1708.84 407.82,1710.25 406.55,1713.31 406.55,1717.29 407.82,1720.35 409.23,1721.76 410.63,1723.16 413.69,1724.43 414.73,1724.43 415.68,1724.83 710.32,1724.83
  pour cut-out: 1119.85,1713.9 1120.89,1713.9 1122.39,1713.28 1124.27,1711.4 1125.21,1710.46 1125.83,1708.96 1125.83,1707.92 1126.23,1706.97 1126.23,1701.06 1125.83,1700.11 1125.83,1699.07 1125.21,1697.57 1123.33,1695.69 1122.39,1694.76 1120.89,1694.13 1119.85,1694.13 1118.9,1693.74 1111.03,1693.74 1110.07,1694.13 1109.04,1694.13 1107.53,1694.76 1105.66,1696.63 1104.72,1697.57 1104.14,1698.98 1103.55,1697.57 1101.68,1695.69 1100.74,1694.76 1099.23,1694.13 1098.2,1694.13 1097.25,1693.74 1089.37,1693.74 1088.42,1694.13 1087.38,1694.13 1085.88,1694.76 1084,1696.63 1083.07,1697.57 1082.44,1699.07 1082.44,1700.11 1082.05,1701.06 1082.05,1706.97 1082.44,1707.92 1082.44,1708.96 1083.07,1710.46 1084.94,1712.34 1085.88,1713.28 1087.38,1713.9 1088.42,1713.9 1089.37,1714.29 1097.25,1714.29 1098.2,1713.9 1099.23,1713.9 1100.74,1713.28 1102.62,1711.4 1103.55,1710.46 1104.14,1709.06 1104.72,1710.46 1106.59,1712.34 1107.53,1713.28 1109.04,1713.9 1110.07,1713.9 1111.03,1714.29 1118.9,1714.29
  pour cut-out: 735.99,2003.51 739.05,2002.24 740.46,2000.83 741.86,1999.43 743.13,1996.37 743.13,1995.33 743.53,1994.38 743.53,1738.18 743.13,1737.23 743.13,1736.19 741.86,1733.13 740.46,1731.73 739.05,1730.32 735.99,1729.05 732.01,1729.05 728.95,1730.32 727.54,1731.73 726.14,1733.13 724.87,1736.19 724.87,1737.23 724.47,1738.18 724.47,1994.38 724.87,1995.33 724.87,1996.37 726.14,1999.43 727.54,2000.83 728.95,2002.24 732.01,2003.51 735.99,2003.51
  pour cut-out: 1137.27,1737.31 1138.3,1737.31 1139.81,1736.69 1141.68,1734.82 1142.62,1733.88 1143.24,1732.37 1143.24,1731.34 1143.64,1730.38 1143.64,1722.51 1143.24,1721.56 1143.24,1720.52 1142.62,1719.02 1140.75,1717.14 1139.81,1716.2 1138.3,1715.58 1137.27,1715.58 1136.31,1715.18 1130.41,1715.18 1129.45,1715.58 1128.42,1715.58 1126.91,1716.2 1126.2,1716.92 1115.9,1716.92 1114.95,1717.32 1113.91,1717.32 1110.85,1718.59 1109.45,1719.99 1108.04,1721.4 1106.77,1724.46 1106.77,1728.44 1108.04,1731.5 1109.45,1732.9 1110.85,1734.31 1113.91,1735.58 1114.95,1735.58 1115.9,1735.97 1126.19,1735.97 1126.91,1736.69 1128.42,1737.31 1129.45,1737.31 1130.41,1737.71 1136.31,1737.71
  pour cut-out: 4239.05,1771.4 4240.08,1771.4 4241.59,1770.78 4242.31,1770.06 4477.98,1770.06 4478.88,1770.43 4479.91,1770.43 4480.87,1770.83 4488.74,1770.83 4489.69,1770.43 4490.73,1770.43 4491.89,1769.95 4514.2,1769.95 4515.25,1770.38 4516.28,1770.38 4517.24,1770.78 4525.11,1770.78 4526.07,1770.38 4527.1,1770.38 4528.61,1769.76 4530.48,1767.88 4531.42,1766.95 4532.04,1765.44 4532.04,1764.41 4532.44,1763.45 4532.44,1757.55 4532.04,1756.59 4532.04,1755.56 4531.42,1754.05 4529.54,1752.18 4528.61,1751.24 4528.6,1751.24 4527.1,1750.62 4526.06,1750.62 4525.11,1750.22 4517.24,1750.22 4516.28,1750.62 4515.25,1750.62 4514.56,1750.9 4491.29,1750.9 4490.73,1750.67 4489.69,1750.67 4488.74,1750.27 4480.87,1750.27 4479.91,1750.67 4478.88,1750.67 4478.05,1751.01 4242.31,1751.01 4241.59,1750.29 4240.08,1749.67 4239.05,1749.67 4238.09,1749.27 4232.19,1749.27 4231.23,1749.67 4230.2,1749.67 4228.69,1750.29 4226.82,1752.17 4225.88,1753.1 4225.26,1754.61 4225.26,1755.64 4224.86,1756.6 4224.86,1764.47 4225.26,1765.43 4225.26,1766.46 4225.88,1767.97 4227.75,1769.84 4228.69,1770.78 4230.2,1771.4 4231.23,1771.4 4232.19,1771.8 4238.09,1771.8
  pour cut-out: 3508.87,2084.19 3512.81,2088.13 3515.65,2088.13 3515.65,2055.78 3513.16,2053.29 3510.22,2053.29 3508.87,2054.64
  pour cut-out: 2939.26,2868.29 2939.61,2868.63 2939.61,2962.88 2916.21,2986.27 2916.21,2993.61 2856.06,3053.76 2825.75,3053.76 2825.75,3035.67 2828.43,3032.99 2843.35,3032.99 2846.08,3030.26 2866.16,3030.26 2868.04,3028.37 2868.04,2997.24 2871.67,2993.62 2897.7,2993.62 2916.95,2974.37 2916.95,2885.57 2917.84,2885.57 2935.13,2868.29
  pour cut-out: 2894.47,2232.76 2894.07,2232.37 2894.07,2369.75 2899.31,2369.75 2903.53,2365.53 2903.53,2358.01 2928.31,2333.24 2957.85,2333.24 2979.4,2354.78 2979.4,2299.93 2966.79,2312.55 2959.25,2312.55 2957.38,2314.42 2914.71,2314.42 2900.31,2300.02 2900.31,2249.81 2917.36,2232.76
  pour cut-out: 3042.88,2769.25 3423.79,2388.34 3432.25,2388.34 3432.25,2392.37 3055.37,2769.25
  region net GND: 4669.29,1826.5 4676.57,1826.5 4676.57,1787.13 4669.29,1787.13
  pour cut-out: 1232.58,1407.62 1244.31,1407.61 1244.31,1460.56 1244.89,1461.13 1240.96,1465.06 1239.53,1465.06 1230.59,1456.11 1232.58,1454.12
  pour cut-out: 1082.52,1586.53 1084.07,1589.22 1086.3,1591.46 1112.85,1606.78 1115.66,1609.6 1115.32,1615.37 1114.24,1616.45 1106.97,1616.45 1077.65,1600.23 1082.52,1595.36 1077.65,1600.23
  pour cut-out: 3205.15,1753.38 3202.11,1750.35 3202.11,1707.3 3209.99,1707.3 3209.99,1751.7 3208.3,1753.38
  pour cut-out: 3656.99,2611.72 3643.8,2598.52 3643.8,2597.17 3641.65,2597.17 3639.19,2599.63 3639.67,2600.11 3639.67,2611.72
  pour cut-out: 1611.13,1699.88 1603.01,1691.76 1595.67,1691.76 1593.27,1694.16 1563.35,1694.16 1557.66,1688.47 1557.66,1680.24 1529.59,1680.24 1527.69,1682.14 1527.69,1684.87 1528,1684.87 1547.27,1704.14 1570.59,1704.14 1570.59,1714.14 1577.74,1714.14 1577.74,1701.87 1609.14,1701.87 1611.13,1699.88
  pour cut-out: 3896.81,1899.02 3895.4,1897.62 3895.4,1896.18 3895.11,1896.18 3893.02,1894.09 3865.87,1878.21 3857.86,1870.19 3857.86,1865 3857.09,1864.23 3857.09,1861.11 3857.38,1860.43 3859.06,1859.6 3861.79,1859.6 3865.61,1863.42 3865.61,1864.49 3865.9,1864.49 3868.54,1866.35 3885.74,1876.82 3898.67,1884.29 3907.63,1883.65 3901.68,1894.15
  pour cut-out: 2952.97,3032.98 2914.02,3032.99 2913.97,3032.94 2933.04,3013.87 2935.28,3013.87 2939.45,3018.03 2939.45,3028.31 2948.3,3028.31
  region net NetANT1_1: 4676.57,1769.41 4676.57,1751.3 4662.01,1751.3 4662.01,1769.41
  region: 4669.29,1913.11 4676.57,1913.11 4676.57,1873.74 4669.29,1873.74 4669.29,1909.16
  pour cut-out: 2981.88,3045.07 2995.62,3045.07 2995.62,3032.99 2981.97,3032.99 2981.83,3033.12 2981.83,3045.01
  pour cut-out: 1226.13,1501.09 1229.79,1497.43 1227.89,1495.54 1227.89,1490.54 1205.49,1468.14 1205.49,1455.64 1196.07,1446.23 1190.68,1446.23 1190.68,1483.43 1203.75,1496.51 1221.54,1496.51
  pour cut-out: 1047.6,1369.13 1045.69,1371.04 1042.98,1371.04 1025.28,1353.34 1025.28,1285.68 1047.13,1285.68 1047.6,1286.14
  pour cut-out: 3718.15,1979.68 3721.81,1976.02 3732.91,1987.13 3737.72,1987.13 3737.72,2000.7 3732.81,2005.61 3722.74,2005.61 3722.74,1984.27
  pour cut-out: 3082.94,2333.27 3081.37,2335.92 3081.37,2297.65 3108.58,2297.65 3111.45,2300.52 3111.45,2305.82
  pour cut-out: 3020.3,2327.47 3020.3,2319.72 3051.92,2319.72 3051.92,2280.92 3079.49,2280.92 3081.37,2282.81 3081.37,2358.58 3079.49,2360.47 3051.92,2360.47 3051.92,2327.47
  pour cut-out: 1548.97,1969.59 1548.97,1957.9 1549.36,1957.5 2532.66,1957.5 2532.66,1958.11 2538.8,1964.26 2537.24,1965.82 2537.24,1968.67 1549.89,1968.67
  text ".Layer_Name" at 577,-858.49 h60
Signal Layer 1:
  pour cut-out: 4167.09,1484.19 ccw(c4215.09,1484.19) 4215.09,1436.19 ccw(c4215.09,1484.19) 4263.09,1484.19 ccw(c4215.09,1484.19) 4215.09,1532.19 ccw(c4215.09,1484.19)
  pour cut-out: 734,1946.38 cw(c734,1994.38) 686,1994.38 cw(c734,1994.38) 734,2042.38 cw(c734,1994.38) 782,1994.38 cw(c734,1994.38)
Bottom Layer:
  pour cut-out: 3324.69,1372.94 3324.69,1374.65 3438.58,1488.54 3443.61,1488.54 3446.44,1485.71 3446.44,1482.26 3331.22,1367.04 3324.69,1371.81
  pour cut-out: 2342,2655.17 2342,2634.72 2349.57,2634.72 2359.25,2625.04 2359.25,2620.33 2498.78,2480.79 2498.78,2480.69 2502.88,2480.69 2505.78,2483.59 2505.78,2491.39
  pour cut-out: 3875.69,1563.14 3889.81,1563.14 3889.55,1562.89 3889.55,1389.97 3878.55,1389.97 3875.69,1387.12
  pour cut-out: 3430.94,1952.76 3430.94,1941.83 3429.49,1940.38 3268.73,1940.38 3258.86,1950.25 3261.76,1953.15 3261.76,1957.25 3426.45,1957.25
  pour cut-out: 3258.98,1916.85 3255.54,1913.41 3255.54,1908.2 3398.96,1908.2 3405.96,1915.2 3404.32,1916.85
  text ".Layer_Name" at 577,-858.49 h60

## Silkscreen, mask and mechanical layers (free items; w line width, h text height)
Top Overlay:
  text "<WM2" at 3167.26,3293.2 h30
  text "WM1>" at 3722.72,3288.65 h30
  text "WM2" at 877.14,2175.06 h60
  text "WM1" at 2794.57,2057.74 h60
  text "TI WBMS - CC2662RQ1-BCU-EVM" at 848.95,142.15 h70
  text "Rev. .PCB_Rev" at 1433.42,118.12 h60
  text "MCU122" at 963.68,108.43 h60
  text ".Layer_Name" at 577,-858.49 h60
Bottom Overlay:
  text ".Layer_Name" at 577,-858.49 h60
Top Paste:
  text ".Layer_Name" at 577,-858.49 h60
Bottom Paste:
  text ".Layer_Name" at 577,-858.49 h60
Top Solder:
  text ".Layer_Name" at 577,-858.49 h60
  text ".Layer_Name" at 577,-858.49 h60
Bottom Solder:
  text ".Layer_Name" at 577,-858.49 h60
Drill Guide:
  text ".Layer_Name" at 577,-858.49 h60
M1 Board Outline:
  lines w10: 0,3450 4950,3450 4950,0 0,0 0,3453
  text ".Layer_Name" at 577,-858.49 h60
M2 Board Dimensions:
  rectangle: 0,-275 125,-150
  rectangle: 125,-400 500,-275
  lines w7: 0,-275 1000,-275 ; 125,-400 125,-150 ; 250,-400 250,-150 ; 500,-400 500,-150 ; 750,-400 750,-150 ; 0,-400 1000,-400 1000,-150 0,-150 0,-400
  text ".Layer_Name" at 577,-858.49 h60
M3 3D STEP Top:
  text ".Layer_Name" at 577,-858.49 h60
M4 3D STEP Bottom:
  text ".Layer_Name" at 577,-858.49 h60
M5 Assembly Top:
  lines w10: -292,-930.17 6308,-930.17 ; -292,-726.83 6310,-726.83 ; -292,-523.5 -292,-1133.5 3713,-1133.5 6310,-1133.5 6310,-523.5 -291.5,-523.5 -291.5,-1133.5 1284,-1133.5 ; 2173,-1133.5 2173,-523.5 ; 3440,-726.83 3440,-523.5 ; 4280,-726.83 4280,-523.5 ; 4902,-1140 4902,-937.17
  text "COMPONENTS MARKED 'DNP' SHOULD NOT BE POPULATED." at 1153.5,-318.5 h60
  text "ASSEMBLY VARIANT:" at 1153,-434 h60
  text ".VariantName" at 2189,-434 h60
  text "PCB VIEWED FROM TOP SIDE" at -228.5,-655.67 h60
  text "BOARD #:" at 2248,-655.67 h60
  text ".PRJ_Number" at 2793.5,-655.67 h60
  text "REV:" at 3638,-655.67 h60
  text ".PCB_Rev" at 3929.5,-655.67 h60
  text "SVN REV:" at 4476,-655.67 h60
  text ".VersionControl_RevNumber" at 4982,-655.67 h60
  text "TID #:" at 2248,-859 h60
  text ".TID" at 2793.5,-859 h60
  text "PLOT NAME =" at -228.5,-1064.34 h60
  text ".plot_File_Name" at 577,-1064.34 h60
  text "GENERATED    :" at 2250,-1064.34 h60
  text ".Print_Date" at 3119.5,-1064.34 h60
  text ".Print_Time" at 3848.5,-1064.34 h60
  text "TEXAS INSTRUMENTS" at 5113,-1064.34 h60
M6 Assembly Bottom:
  lines w10: -292.5,-727.33 6309.5,-727.33 ; -290.5,-930.67 6309.5,-930.67 ; 1115.5,-1140.5 1115.5,-937.67 ; 1737.5,-727.33 1737.5,-524 ; 2577.5,-727.33 2577.5,-524 ; 3844.5,-1134 3844.5,-524 ; 4733.5,-1134 6309,-1134 6309,-524 -292.5,-524 -292.5,-1134 2304.5,-1134 6309.5,-1134 6309.5,-524
  text "COMPONENTS MARKED 'DNP' SHOULD NOT BE POPULATED." at 6102,-318 h60
  text ".VariantName" at 5058,-434 h60
  text "ASSEMBLY VARIANT:" at 6097,-434 h60
  text ".VersionControl_RevNumber" at 1035.5,-656.17 h60
  text "SVN REV:" at 1541.5,-656.17 h60
  text ".PCB_Rev" at 2088,-656.17 h60
  text "REV:" at 2379.5,-656.17 h60
  text ".PRJ_Number" at 3224,-656.17 h60
  text "BOARD #:" at 3769.5,-656.17 h60
  text "PCB VIEWED FROM BOTTOM SIDE" at 6246,-656.17 h60
  text ".TID" at 3224,-859.5 h60
  text "TID #:" at 3769.5,-859.5 h60
  text "TEXAS INSTRUMENTS" at 904.5,-1064.84 h60
  text ".Print_Time" at 2169,-1064.84 h60
  text ".Print_Date" at 2898,-1064.84 h60
  text "GENERATED    :" at 3767.5,-1064.84 h60
  text ".plot_File_Name" at 5440.5,-1064.84 h60
  text "PLOT NAME =" at 6246,-1064.84 h60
